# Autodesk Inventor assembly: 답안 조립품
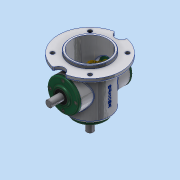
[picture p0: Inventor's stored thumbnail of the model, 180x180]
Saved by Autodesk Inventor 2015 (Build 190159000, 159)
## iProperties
Created: 2018-04
Part Number: 답안 조립품
Document SubType Name: Assembly
Designer: SCD-A03
Author: SCD-A03
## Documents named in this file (16)
- C:\Users\SCD-A03\Desktop\480407V1008\답안 조립품.iam
- C:\Users\SCD-A03\Desktop\480407V1008\본체.ipt
- C:\Users\SCD-A03\Desktop\480407V1008\커버.ipt
- C:\Users\SCD-A03\Desktop\480407V1008\베어링 6203.ipt
- C:\Users\SCD-A03\Desktop\480407V1008\오일 실.ipt
- 오일 실.ipt
- C:\Users\SCD-A03\Desktop\480407V1008\메인 축.ipt
- 메인 축.ipt
- C:\Users\SCD-A03\Desktop\480407V1008\키 5x5.ipt
- C:\Users\SCD-A03\Desktop\480407V1008\메인 베벨기어.ipt
- C:\Users\SCD-A03\Desktop\480407V1008\서브 축.ipt
- 서브 축.ipt
- C:\Users\SCD-A03\Desktop\480407V1008\키 4x4.ipt
- C:\Users\SCD-A03\Desktop\480407V1008\서브 베벨기어.ipt
- C:\Users\SCD-A03\Desktop\480407V1008\볼트 M4.ipt
- 볼트 M4.ipt
